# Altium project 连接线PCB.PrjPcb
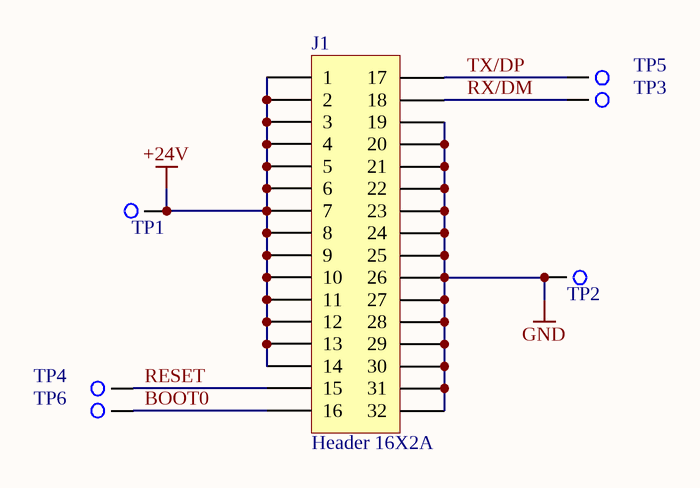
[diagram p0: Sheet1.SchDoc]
1 sheet, 7 parts. Net scope: global (net labels, ports and power ports of the same name join across sheets).
Board file: V0-CON-WR V2.0.PcbDoc

## Sheet Sheet1.SchDoc
size A4; SheetNumber: 1; SheetTotal: 1

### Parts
J1  Header 16X2A  [BTB_2x16_0.5mm]
TP1  Testpoint 1.6mm  [Testpoint 1.6mm]  (value not drawn)
TP2  Testpoint 1.6mm  [Testpoint 1.6mm]  (value not drawn)
TP3  Testpoint 1.6mm  [Testpoint 1.6mm]  (value not drawn)
TP4  Testpoint 1.6mm  [Testpoint 1.6mm]  (value not drawn)
TP5  Testpoint 1.6mm  [Testpoint 1.6mm]  (value not drawn)
TP6  Testpoint 1.6mm  [Testpoint 1.6mm]  (value not drawn)

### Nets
+24V: J1.1 J1.2 J1.3 J1.4 J1.5 J1.6 J1.7 J1.8 J1.9 J1.10 J1.11 J1.12 J1.13 J1.14 TP1.1
GND: J1.19 J1.20 J1.21 J1.22 J1.23 J1.24 J1.25 J1.26 J1.27 J1.28 J1.29 J1.30 J1.31 J1.32 TP2.1
BOOT0: J1.16 TP6.1
RESET: J1.15 TP4.1
RX/DM: J1.18 TP3.1
TX/DP: J1.17 TP5.1

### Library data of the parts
J1 = Header 16X2A: Header, 16-Pin, Dual row
TP1-TP6 = Testpoint 1.6mm: ID: Library_MISC-0001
